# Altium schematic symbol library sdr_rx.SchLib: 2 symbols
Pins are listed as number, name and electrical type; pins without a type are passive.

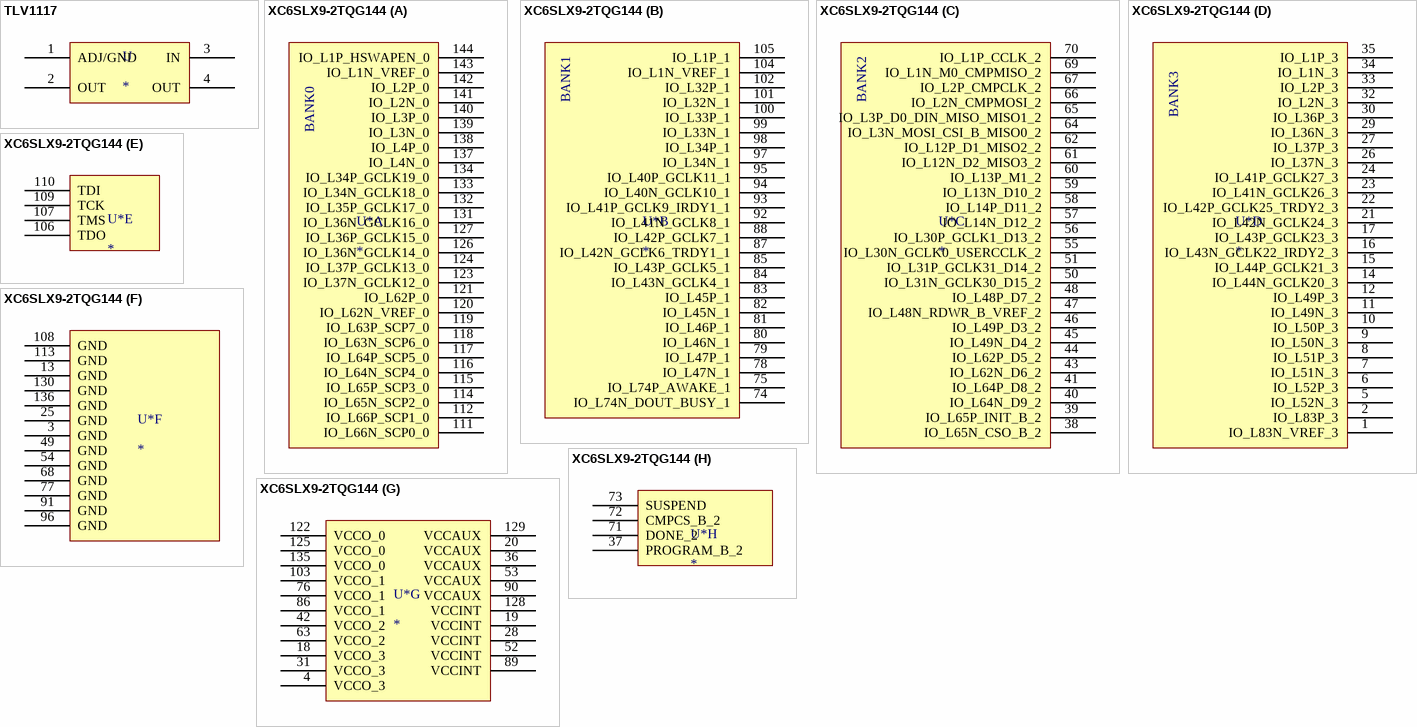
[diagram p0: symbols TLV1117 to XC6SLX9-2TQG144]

## TLV1117
designator U
footprint SOT230P700X180-4N (SOT223, 4-Leads, Body 6.7x7.3mm (max), Pitch 2.30mm, IPC Medium Density)
pins: 1 ADJ/GND, 2 OUT, 3 IN, 4 OUT

## XC6SLX9-2TQG144
designator U*
footprint TSQFP50P2200X2200X160-144N (TSQFP, 144-Leads, Body 22.0x22.0mm (max), Pitch 0.50mm, IPC Medium Density)
part A pins: 111 IO_L66N_SCP0_0, 112 IO_L66P_SCP1_0, 114 IO_L65N_SCP2_0, 115 IO_L65P_SCP3_0, 116 IO_L64N_SCP4_0, 117 IO_L64P_SCP5_0, 118 IO_L63N_SCP6_0, 119 IO_L63P_SCP7_0, 120 IO_L62N_VREF_0, 121 IO_L62P_0, 123 IO_L37N_GCLK12_0, 124 IO_L37P_GCLK13_0, 126 IO_L36N_GCLK14_0, 127 IO_L36P_GCLK15_0, 131 IO_L36N_GCLK16_0, 132 IO_L35P_GCLK17_0, 133 IO_L34N_GCLK18_0, 134 IO_L34P_GCLK19_0, 137 IO_L4N_0, 138 IO_L4P_0, 139 IO_L3N_0, 140 IO_L3P_0, 141 IO_L2N_0, 142 IO_L2P_0, 143 IO_L1N_VREF_0, 144 IO_L1P_HSWAPEN_0
part B pins: 74 IO_L74N_DOUT_BUSY_1, 75 IO_L74P_AWAKE_1, 78 IO_L47N_1, 79 IO_L47P_1, 80 IO_L46N_1, 81 IO_L46P_1, 82 IO_L45N_1, 83 IO_L45P_1, 84 IO_L43N_GCLK4_1, 85 IO_L43P_GCLK5_1, 87 IO_L42N_GCLK6_TRDY1_1, 88 IO_L42P_GCLK7_1, 92 IO_L41N_GCLK8_1, 93 IO_L41P_GCLK9_IRDY1_1, 94 IO_L40N_GCLK10_1, 95 IO_L40P_GCLK11_1, 97 IO_L34N_1, 98 IO_L34P_1, 99 IO_L33N_1, 100 IO_L33P_1, 101 IO_L32N_1, 102 IO_L32P_1, 104 IO_L1N_VREF_1, 105 IO_L1P_1
part C pins: 38 IO_L65N_CSO_B_2, 39 IO_L65P_INIT_B_2, 40 IO_L64N_D9_2, 41 IO_L64P_D8_2, 43 IO_L62N_D6_2, 44 IO_L62P_D5_2, 45 IO_L49N_D4_2, 46 IO_L49P_D3_2, 47 IO_L48N_RDWR_B_VREF_2, 48 IO_L48P_D7_2, 50 IO_L31N_GCLK30_D15_2, 51 IO_L31P_GCLK31_D14_2, 55 IO_L30N_GCLK0_USERCCLK_2, 56 IO_L30P_GCLK1_D13_2, 57 IO_L14N_D12_2, 58 IO_L14P_D11_2, 59 IO_L13N_D10_2, 60 IO_L13P_M1_2, 61 IO_L12N_D2_MISO3_2, 62 IO_L12P_D1_MISO2_2, 64 IO_L3N_MOSI_CSI_B_MISO0_2, 65 IO_L3P_D0_DIN_MISO_MISO1_2, 66 IO_L2N_CMPMOSI_2, 67 IO_L2P_CMPCLK_2, 69 IO_L1N_M0_CMPMISO_2, 70 IO_L1P_CCLK_2
part D pins: 1 IO_L83N_VREF_3, 2 IO_L83P_3, 5 IO_L52N_3, 6 IO_L52P_3, 7 IO_L51N_3, 8 IO_L51P_3, 9 IO_L50N_3, 10 IO_L50P_3, 11 IO_L49N_3, 12 IO_L49P_3, 14 IO_L44N_GCLK20_3, 15 IO_L44P_GCLK21_3, 16 IO_L43N_GCLK22_IRDY2_3, 17 IO_L43P_GCLK23_3, 21 IO_L42N_GCLK24_3, 22 IO_L42P_GCLK25_TRDY2_3, 23 IO_L41N_GCLK26_3, 24 IO_L41P_GCLK27_3, 26 IO_L37N_3, 27 IO_L37P_3, 29 IO_L36N_3, 30 IO_L36P_3, 32 IO_L2N_3, 33 IO_L2P_3, 34 IO_L1N_3, 35 IO_L1P_3
part E pins: 106 TDO, 107 TMS, 109 TCK, 110 TDI
part F pins: 3 GND, 13 GND, 25 GND, 49 GND, 54 GND, 68 GND, 77 GND, 91 GND, 96 GND, 108 GND, 113 GND, 130 GND, 136 GND
part G pins: 4 VCCO_3, 18 VCCO_3, 19 VCCINT, 20 VCCAUX, 28 VCCINT, 31 VCCO_3, 36 VCCAUX, 42 VCCO_2, 52 VCCINT, 53 VCCAUX, 63 VCCO_2, 76 VCCO_1, 86 VCCO_1, 89 VCCINT, 90 VCCAUX, 103 VCCO_1, 122 VCCO_0, 125 VCCO_0, 128 VCCINT, 129 VCCAUX, 135 VCCO_0
part H pins: 37 PROGRAM_B_2, 71 DONE_2, 72 CMPCS_B_2, 73 SUSPEND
